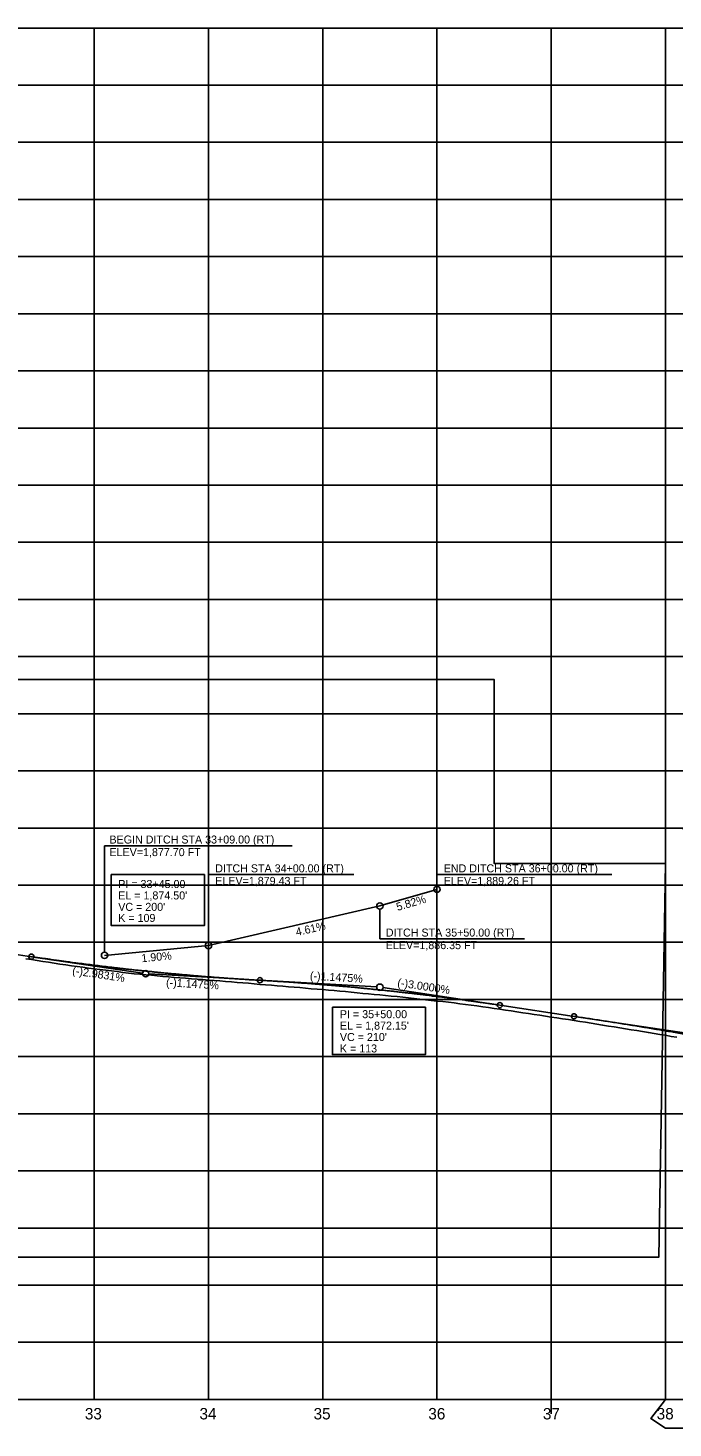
# Model space of a CAD drawing. Extents: x 553912 to 567693, y 512355 to 537539.
# Drawn here: x 559491 to 560056, y 513580 to 514805 of the extents above; entities that cross this region are included whole.
import ezdxf

# ---------------------------------------------------------------- set-up
doc = ezdxf.new("R2010")
doc.units = 0
for name, color, linetype in [('Exist Profile Cell', 7, 'Continuous'), ('Exist Vertical Profile Ground Line', 7, 'Continuous'), ('Exist Vertical Profile Horizontal Axis Label Major', 7, 'Continuous'), ('Prop Vertical Profile Curve Label', 7, 'Continuous'), ('Prop Vertical Profile Ditch Grade Right', 7, 'Continuous'), ('Prop Vertical Profile Ditch Grade Right Label', 7, 'Continuous'), ('Prop Vertical Profile Grade', 7, 'Continuous'), ('Prop Vertical Profile Grade Label', 7, 'Continuous'), ('Prop VPI Label', 7, 'Continuous'), ('Scratch_Level_1', 7, 'Continuous'), ('Scratch_Level_5', 7, 'Continuous'), ('Sheet Profile Grid Major CELL', 7, 'Continuous')]:
    doc.layers.add(name, color=color, linetype=linetype)

msp = doc.modelspace()

# ---------------------------------------------------------------- linework, layer by layer
at = {"layer": 'Exist Profile Cell'}
msp.add_line((557249.5, 513605.4), (563849.5, 513605.4), dxfattribs=at)
msp.add_line((557249.5, 513605.4), (563849.5, 513605.4), dxfattribs=at)
at = {"layer": 'Exist Vertical Profile Ground Line'}
for points in [[(559489.5, 513990.9), (559494.5, 513990.2), (559499.5, 513989.5), (559504.5, 513988.7), (559509.5, 513988), (559514.5, 513987.2), (559519.5, 513986.4), (559524.5, 513985.7), (559529.5, 513984.9), (559534.5, 513984.2), (559539.5, 513983.5), (559544.5, 513982.8), (559549.5, 513982.2), (559554.5, 513981.6), (559559.5, 513980.9), (559564.5, 513980.3), (559569.5, 513979.7), (559574.5, 513979), (559579.5, 513978.4), (559584.5, 513977.9), (559589.5, 513977.4), (559594.5, 513977), (559599.5, 513976.5), (559604.5, 513976), (559609.5, 513975.5), (559614.5, 513975.1), (559619.5, 513974.7), (559624.5, 513974.3), (559629.5, 513973.9), (559634.5, 513973.5), (559639.5, 513973.1), (559644.5, 513972.8), (559649.5, 513972.4), (559654.5, 513972), (559659.5, 513971.6), (559664.5, 513971.2), (559669.5, 513970.8), (559674.5, 513970.3), (559679.5, 513969.9), (559684.5, 513969.5), (559689.5, 513969.1), (559694.5, 513968.6), (559699.5, 513968.2), (559704.5, 513967.8), (559709.5, 513967.4), (559714.5, 513967), (559719.5, 513966.5), (559724.5, 513966.1), (559729.5, 513965.7), (559734.5, 513965.3), (559739.5, 513964.8), (559744.5, 513964.4), (559749.5, 513964)], [(559489.5, 513990.9), (559494.5, 513990.2), (559499.5, 513989.5), (559504.5, 513988.7), (559509.5, 513988), (559514.5, 513987.2), (559519.5, 513986.4), (559524.5, 513985.7), (559529.5, 513984.9), (559534.5, 513984.2), (559539.5, 513983.5), (559544.5, 513982.8), (559549.5, 513982.2), (559554.5, 513981.6), (559559.5, 513980.9), (559564.5, 513980.3), (559569.5, 513979.7), (559574.5, 513979), (559579.5, 513978.4), (559584.5, 513977.9), (559589.5, 513977.4), (559594.5, 513977), (559599.5, 513976.5), (559604.5, 513976), (559609.5, 513975.5), (559614.5, 513975.1), (559619.5, 513974.7), (559624.5, 513974.3), (559629.5, 513973.9), (559634.5, 513973.5), (559639.5, 513973.1), (559644.5, 513972.8), (559649.5, 513972.4), (559654.5, 513972), (559659.5, 513971.6), (559664.5, 513971.2), (559669.5, 513970.8), (559674.5, 513970.3), (559679.5, 513969.9), (559684.5, 513969.5), (559689.5, 513969.1), (559694.5, 513968.6), (559699.5, 513968.2), (559704.5, 513967.8), (559709.5, 513967.4), (559714.5, 513967), (559719.5, 513966.5), (559724.5, 513966.1), (559729.5, 513965.7), (559734.5, 513965.3), (559739.5, 513964.8), (559744.5, 513964.4), (559749.5, 513964)], [(559749.5, 513964), (559754.5, 513963.6), (559759.5, 513963.1), (559764.5, 513962.7), (559769.5, 513962.3), (559774.5, 513961.8), (559779.5, 513961.2), (559784.5, 513960.7), (559789.5, 513960.3), (559794.5, 513959.8), (559799.5, 513959.4), (559804.5, 513958.9), (559809.5, 513958.4), (559814.5, 513957.9), (559819.5, 513957.3), (559824.5, 513956.8), (559829.5, 513956.2), (559834.5, 513955.7), (559839.5, 513955.1), (559844.5, 513954.6), (559849.5, 513954), (559854.5, 513953.5), (559859.5, 513952.9), (559864.5, 513952.3), (559869.5, 513951.6), (559874.5, 513951), (559879.5, 513950.4), (559884.5, 513949.8), (559889.5, 513949), (559894.5, 513948.3), (559899.5, 513947.5), (559904.5, 513946.8), (559909.5, 513946), (559914.5, 513945.3), (559919.5, 513944.5), (559924.5, 513943.8), (559929.5, 513943), (559934.5, 513942.3), (559939.5, 513941.5), (559944.5, 513940.8), (559949.5, 513940), (559954.5, 513939.3), (559959.5, 513938.5), (559964.5, 513937.7), (559969.5, 513937), (559974.5, 513936.2), (559979.5, 513935.4), (559984.5, 513934.6), (559989.5, 513933.8), (559994.5, 513933), (559999.5, 513932.1), (560004.5, 513931.3), (560009.5, 513930.5), (560014.5, 513929.7), (560019.5, 513928.9), (560024.5, 513928.1), (560029.5, 513927.3), (560034.5, 513926.4), (560039.5, 513925.6), (560044.5, 513924.8), (560049.5, 513924), (560054.5, 513923.1), (560059.5, 513922.3)], [(559749.5, 513964), (559754.5, 513963.6), (559759.5, 513963.1), (559764.5, 513962.7), (559769.5, 513962.3), (559774.5, 513961.8), (559779.5, 513961.2), (559784.5, 513960.7), (559789.5, 513960.3), (559794.5, 513959.8), (559799.5, 513959.4), (559804.5, 513958.9), (559809.5, 513958.4), (559814.5, 513957.9), (559819.5, 513957.3), (559824.5, 513956.8), (559829.5, 513956.2), (559834.5, 513955.7), (559839.5, 513955.1), (559844.5, 513954.6), (559849.5, 513954), (559854.5, 513953.5), (559859.5, 513952.9), (559864.5, 513952.3), (559869.5, 513951.6), (559874.5, 513951), (559879.5, 513950.4), (559884.5, 513949.8), (559889.5, 513949), (559894.5, 513948.3), (559899.5, 513947.5), (559904.5, 513946.8), (559909.5, 513946), (559914.5, 513945.3), (559919.5, 513944.5), (559924.5, 513943.8), (559929.5, 513943), (559934.5, 513942.3), (559939.5, 513941.5), (559944.5, 513940.8), (559949.5, 513940), (559954.5, 513939.3), (559959.5, 513938.5), (559964.5, 513937.7), (559969.5, 513937), (559974.5, 513936.2), (559979.5, 513935.4), (559984.5, 513934.6), (559989.5, 513933.8), (559994.5, 513933), (559999.5, 513932.1), (560004.5, 513931.3), (560009.5, 513930.5), (560014.5, 513929.7), (560019.5, 513928.9), (560024.5, 513928.1), (560029.5, 513927.3), (560034.5, 513926.4), (560039.5, 513925.6), (560044.5, 513924.8), (560049.5, 513924), (560054.5, 513923.1), (560059.5, 513922.3)]]:
    msp.add_lwpolyline(points, dxfattribs=at)
at = {"layer": 'Prop Vertical Profile Curve Label'}
for centre in [(559494.5, 513992.8), (559694.5, 513972.2), (559694.5, 513972.2), (559904.5, 513950.4), (559969.5, 513940.6)]:
    msp.add_circle(centre, 2.25, dxfattribs=at)
at = {"layer": 'Prop Vertical Profile Ditch Grade Right'}
msp.add_lwpolyline([(559558.5, 513993.9), (559649.5, 514002.6), (559799.5, 514037.2), (559849.5, 514051.7)], dxfattribs=at)
at = {"layer": 'Prop Vertical Profile Ditch Grade Right Label'}
for p, q in [((559558.5, 514089.8), (559558.5, 513996.7)), ((559722.8, 514089.8), (559558.5, 514089.8)), ((559776.8, 514064.6), (559649.5, 514064.6)), ((559649.5, 514005.3), (559649.5, 514064.6)), ((559849.5, 514054.5), (559849.5, 514064.6)), ((560002.6, 514064.6), (559849.5, 514064.6)), ((559799.5, 514034.4), (559799.5, 514008.4)), ((559926.1, 514008.4), (559799.5, 514008.4))]:
    msp.add_line(p, q, dxfattribs=at)
for centre in [(559849.5, 514051.7), (559799.5, 514037.2), (559649.5, 514002.6), (559558.5, 513993.9)]:
    msp.add_circle(centre, 2.75, dxfattribs=at)
at = {"layer": 'Prop Vertical Profile Grade'}
for p, q in [((559409.5, 514005.5), (559494.5, 513992.8)), ((559904.5, 513950.4), (559969.5, 513940.6))]:
    msp.add_line(p, q, dxfattribs=at)
for points in [[(559494.5, 513992.8), (559498.5, 513992.2), (559502.5, 513991.6), (559506.5, 513991.1), (559510.5, 513990.5), (559514.5, 513989.9), (559518.5, 513989.4), (559522.5, 513988.8), (559526.5, 513988.3), (559530.5, 513987.7), (559534.5, 513987.2), (559538.5, 513986.7), (559542.5, 513986.2), (559546.5, 513985.7), (559550.5, 513985.2), (559554.5, 513984.7), (559558.5, 513984.2), (559562.5, 513983.7), (559566.5, 513983.3), (559570.5, 513982.8), (559574.5, 513982.4), (559578.5, 513981.9), (559582.5, 513981.5), (559586.5, 513981), (559590.5, 513980.6), (559594.5, 513980.2), (559598.5, 513979.8), (559602.5, 513979.4), (559606.5, 513979), (559610.5, 513978.6), (559614.5, 513978.2), (559618.5, 513977.8), (559622.5, 513977.5), (559626.5, 513977.1), (559630.5, 513976.8), (559634.5, 513976.4), (559638.5, 513976.1), (559642.5, 513975.8), (559646.5, 513975.4), (559650.5, 513975.1), (559654.5, 513974.8), (559658.5, 513974.5), (559662.5, 513974.2), (559666.5, 513973.9), (559670.5, 513973.7), (559674.5, 513973.4), (559678.5, 513973.1), (559682.5, 513972.9), (559686.5, 513972.6), (559690.5, 513972.4), (559694.5, 513972.2)], [(559694.5, 513972.2), (559698.7, 513971.9), (559702.9, 513971.7), (559707.1, 513971.4), (559711.3, 513971.1), (559715.5, 513970.9), (559719.7, 513970.6), (559723.9, 513970.3), (559728.1, 513970), (559732.3, 513969.7), (559736.5, 513969.4), (559740.7, 513969), (559744.9, 513968.7), (559749.1, 513968.4), (559753.3, 513968), (559757.5, 513967.7), (559761.7, 513967.3), (559765.9, 513966.9), (559770.1, 513966.6), (559774.3, 513966.2), (559778.5, 513965.8), (559782.7, 513965.4), (559786.9, 513965), (559791.1, 513964.6), (559795.3, 513964.1), (559799.5, 513963.7), (559803.7, 513963.3), (559807.9, 513962.8), (559812.1, 513962.4), (559816.3, 513961.9), (559820.5, 513961.4), (559824.7, 513961), (559828.9, 513960.5), (559833.1, 513960), (559837.3, 513959.5), (559841.5, 513959), (559845.7, 513958.4), (559849.9, 513957.9), (559854.1, 513957.4), (559858.3, 513956.8), (559862.5, 513956.3), (559866.7, 513955.7), (559870.9, 513955.2), (559875.1, 513954.6), (559879.3, 513954), (559883.5, 513953.4), (559887.7, 513952.8), (559891.9, 513952.2), (559896.1, 513951.6), (559900.3, 513951), (559904.5, 513950.4)], [(559969.5, 513940.6), (559975.5, 513939.7), (559981.5, 513938.8), (559987.5, 513937.9), (559993.5, 513937), (559999.5, 513936), (560005.5, 513935.1), (560011.5, 513934.1), (560017.5, 513933.2), (560023.5, 513932.2), (560029.5, 513931.2), (560035.5, 513930.2), (560041.5, 513929.2), (560047.5, 513928.2), (560053.5, 513927.2), (560059.5, 513926.1), (560065.5, 513925.1), (560071.5, 513924), (560077.5, 513923), (560083.5, 513921.9), (560089.5, 513920.8), (560095.5, 513919.8), (560101.5, 513918.7), (560107.5, 513917.6), (560113.5, 513916.4), (560119.5, 513915.3), (560125.5, 513914.2), (560131.5, 513913.1), (560137.5, 513911.9), (560143.5, 513910.8), (560149.5, 513909.6), (560155.5, 513908.4), (560161.5, 513907.2), (560167.5, 513906), (560173.5, 513904.8), (560179.5, 513903.6), (560185.5, 513902.4), (560191.5, 513901.2), (560197.5, 513899.9), (560203.5, 513898.7), (560209.5, 513897.4), (560215.5, 513896.2), (560221.5, 513894.9), (560227.5, 513893.6), (560233.5, 513892.3), (560239.5, 513891), (560245.5, 513889.7), (560251.5, 513888.4), (560257.5, 513887.1), (560263.5, 513885.7), (560269.5, 513884.4)]]:
    msp.add_spline(points, degree=3, dxfattribs=at)
at = {"layer": 'Prop VPI Label'}
for p, q in [((559494.5, 513992.8), (559591.7, 513978.3)), ((559694.5, 513972.2), (559597.2, 513977.7)), ((559694.5, 513972.2), (559796.7, 513966.3)), ((559904.5, 513950.4), (559802.2, 513965.7)), ((559969.5, 513940.6), (560116.7, 513918.5))]:
    msp.add_line(p, q, dxfattribs=at)
for points in [[(559564.3, 514064.7), (559645.9, 514064.7), (559645.9, 514020), (559564.3, 514020)], [(559757.9, 513948.6), (559839.4, 513948.6), (559839.4, 513907.1), (559757.9, 513907.1)]]:
    msp.add_lwpolyline(points, close=True, dxfattribs=at)
for centre in [(559594.5, 513977.9), (559799.5, 513966.1)]:
    msp.add_circle(centre, 2.75, dxfattribs=at)
at = {"layer": 'Scratch_Level_1'}
msp.add_line((559949.5, 513592.9), (559949.5, 514191.2), dxfattribs=at)
at = {"layer": 'Scratch_Level_5'}
for points in [[(558649.5, 514235.4), (558643.8, 513729.9), (560043.8, 513729.9), (560049.5, 514074.4), (559899.4, 514074.4), (559899.4, 514235.4)], [(561299.4, 514080.4), (560049.5, 514105.4), (560049.5, 513605.4), (560036.6, 513588.8), (560049.5, 513580.4), (561449.5, 513580.4), (561462.7, 513590.1), (561449.5, 513605.4), (561449.5, 513944.4), (561299.4, 513944.4)]]:
    msp.add_lwpolyline(points, close=True, dxfattribs=at)
at = {"layer": 'Sheet Profile Grid Major CELL'}
for p, q in [((563849.5, 514805.4), (557249.5, 514805.4)), ((559549.5, 513605.4), (559549.5, 514805.4)), ((559649.5, 513605.4), (559649.5, 514805.4)), ((559749.5, 513605.4), (559749.5, 514805.4)), ((559849.5, 513605.4), (559849.5, 514805.4)), ((559949.5, 513605.4), (559949.5, 514805.4)), ((560049.5, 513605.4), (560049.5, 514805.4)), ((563849.5, 514755.4), (557249.5, 514755.4)), ((563849.5, 514705.4), (557249.5, 514705.4)), ((563849.5, 514655.4), (557249.5, 514655.4)), ((563849.5, 514605.4), (557249.5, 514605.4)), ((563849.5, 514555.4), (557249.5, 514555.4)), ((563849.5, 514505.4), (557249.5, 514505.4)), ((563849.5, 514455.4), (557249.5, 514455.4)), ((563849.5, 514405.4), (557249.5, 514405.4)), ((563849.5, 514355.4), (557249.5, 514355.4)), ((563849.5, 514305.4), (557249.5, 514305.4)), ((563849.5, 514255.4), (557249.5, 514255.4)), ((563849.5, 514205.4), (557249.5, 514205.4)), ((563849.5, 514155.4), (557249.5, 514155.4)), ((563849.5, 514105.4), (557249.5, 514105.4)), ((563849.5, 514055.4), (557249.5, 514055.4)), ((563849.5, 514005.4), (557249.5, 514005.4)), ((563849.5, 513955.4), (557249.5, 513955.4)), ((563849.5, 513905.4), (557249.5, 513905.4)), ((563849.5, 513855.4), (557249.5, 513855.4)), ((563849.5, 513805.4), (557249.5, 513805.4)), ((563849.5, 513755.4), (557249.5, 513755.4)), ((563849.5, 513705.4), (557249.5, 513705.4)), ((563849.5, 513655.4), (557249.5, 513655.4))]:
    msp.add_line(p, q, dxfattribs=at)

# ---------------------------------------------------------------- texts
at = {"layer": 'Exist Vertical Profile Horizontal Axis Label Major'}
for s, p in [('33', (559541.3, 513587.9)), ('33', (559541.3, 513587.9)), ('34', (559641.6, 513587.9)), ('34', (559641.6, 513587.9)), ('35', (559741.5, 513587.9)), ('35', (559741.5, 513587.9)), ('36', (559841.9, 513587.9)), ('36', (559841.9, 513587.9)), ('37', (559942.2, 513587.9)), ('37', (559942.2, 513587.9)), ('38', (560041.8, 513587.9)), ('38', (560041.8, 513587.9))]:
    msp.add_text(s, height=10, dxfattribs=at).set_placement(p)
at = {"layer": 'Prop Vertical Profile Curve Label'}
for s, p in [("VC = 200'", (559570.5, 514032.9)), ('K = 109', (559570.5, 514023.2)), ("VC = 210'", (559764.5, 513919)), ('K = 113', (559764.5, 513909))]:
    msp.add_text(s, height=7, dxfattribs=at).set_placement(p)
at = {"layer": 'Prop Vertical Profile Ditch Grade Right'}
for s, p in [('BEGIN DITCH STA 33+09.00 (RT)', (559562.8, 514091.8)), ('DITCH STA 34+00.00 (RT)', (559655.4, 514066.6)), ('END DITCH STA 36+00.00 (RT)', (559855.4, 514066.6)), ('DITCH STA 35+50.00 (RT)', (559804.7, 514010.4))]:
    msp.add_text(s, height=7, dxfattribs=at).set_placement(p)
at = {"layer": 'Prop Vertical Profile Ditch Grade Right Label'}
for s, p in [('ELEV=1,877.70 FT', (559562.8, 514080.8)), ('ELEV=1,879.43 FT', (559655.4, 514055.6)), ('ELEV=1,889.26 FT', (559855.4, 514055.6)), ('ELEV=1,886.35 FT', (559804.7, 513999.4))]:
    msp.add_text(s, height=7, dxfattribs=at).set_placement(p)
for s, rotation, p in [('5.82%', 16.225, (559815, 514032.8)), ('4.61%', 12.989, (559726.7, 514010.8)), ('1.90%', 5.4299, (559591.1, 513987.9))]:
    msp.add_text(s, height=7, rotation=rotation, dxfattribs=at).set_placement(p)
at = {"layer": 'Prop Vertical Profile Grade Label'}
for s, rotation, p in [('(-)2.9831%', 351.5167, (559529.9, 513977.4)), ('(-)1.1475%', 356.7161, (559612.2, 513966.9)), ('(-)1.1475%', 356.7161, (559738.1, 513972.7)), ('(-)3.0000%', 351.4692, (559814.5, 513966.9))]:
    msp.add_text(s, height=7, rotation=rotation, dxfattribs=at).set_placement(p)
at = {"layer": 'Prop VPI Label'}
for s, p in [('PI = 33+45.00', (559570.5, 514052.9)), ("EL = 1,874.50'", (559570.5, 514042.9)), ('PI = 35+50.00', (559764.5, 513939)), ("EL = 1,872.15'", (559764.5, 513929))]:
    msp.add_text(s, height=7, dxfattribs=at).set_placement(p)

doc.saveas('drawing.dxf')
